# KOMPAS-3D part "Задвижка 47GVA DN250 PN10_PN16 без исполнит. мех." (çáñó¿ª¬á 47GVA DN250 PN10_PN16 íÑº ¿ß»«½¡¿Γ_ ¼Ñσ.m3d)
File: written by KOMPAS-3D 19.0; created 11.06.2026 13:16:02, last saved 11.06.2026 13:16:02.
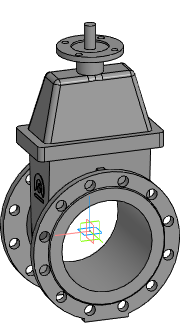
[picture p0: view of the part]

Document properties: Автор: Евгений; Полное имя файла: Z:\3.Личные\kachalov\001_3d для проектировщиков\2.2 Тип 47GVA, 47GVA.Z\_stp\_stp_Задвижка 47GVA DN40-DN1000 без исп.мех\Задвижка 47GVA DN250 PN10_PN16 без исполнит_ мех.m3d

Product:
- Part/product: Задвижка 47GVA DN250 PN10_PN16 без исполнит. мех.

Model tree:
1. Операция без истории:1  (labels: Задвижка 47GVA DN250 PN10_PN16 без исполнит. мех.)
